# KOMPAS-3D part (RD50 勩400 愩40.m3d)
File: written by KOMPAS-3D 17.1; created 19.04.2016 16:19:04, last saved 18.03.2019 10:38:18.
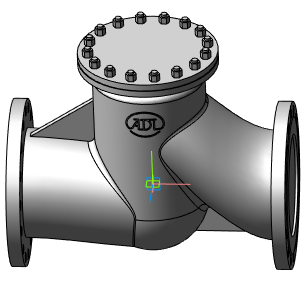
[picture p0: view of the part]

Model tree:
1. Операция без истории:2  (labels: Сталь 20  ГОСТ 1050-88)

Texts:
  RD50 Ду15 Ру40
  RD50 Ду20 Ру40
  RD50 Ду25 Ру40
  RD50 Ду32 Ру40
  RD50 Ду40 Ру40
  RD50 Ду50 Ру40
  RD50 Ду65 Ру40
  RD50 Ду80 Ру40
  RD50 Ду100 Ру40
  RD50 Ду125 Ру40
  RD50 Ду150 Ру40
  RD50 Ду200 Ру40
  RD50 Ду250 Ру40
  RD50 Ду300 Ру40
  RD50 Ду350 Ру40
  RD50 Ду400 Ру40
